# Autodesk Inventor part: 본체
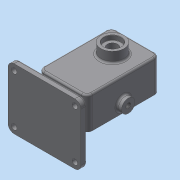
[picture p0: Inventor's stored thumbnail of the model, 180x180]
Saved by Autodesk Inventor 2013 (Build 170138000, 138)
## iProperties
Created: 2020-04
Part Number: 본체
Material: 일반
Document SubType Name: Modeling
Designer: dgall
Density: 1 g/cm^3
Author: dgall
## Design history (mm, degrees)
sketch "스케치1"
  geometry: L1 (-40, 60)-(40, 60); L2 (40, 60)-(40, -60); L3 (40, -60)-(-40, -60); L4 (-40, -60)-(-40, 60); 1 further point
  constraints: 8 end point, 2 parallel, 1 horizontal, 1 perpendicular
  dimensions: "d0" = 80 distance of L1.start L1.end; "d2" = 120 distance of L3.end L1.start; "d3" = 40 distance from line of L4 point (0, 0); "d4" = 60 distance from line of point (0, 0) L1
extrude "돌출1" new body sketch "스케치1" stored distance "d5" = 53; taper "d6" = 0 deg
fillet "모깎기1" dims "d7" = 9
node "작업 평면1"
sketch "스케치2"
  geometry: C1 r 19 at (0, 22); 1 further point
  constraints: 1 centre point, 1 vertical alignment
  dimensions: "d9" = 22 distance of point (0, 0) C1.centre; "d10" = 38 diameter of C1
extrude "돌출2" join sketch "스케치2" stored distance "d11" = 38 (= d10); taper "d12" = 0 deg
sketch "스케치3"
  geometry: L1 (-31, -60)-(31, -60) reference; L2 (-24, 22)-(-24, -22); L3 (24, 22)-(24, -22); A1 r 24 centre (0, 22) between (24, 22) and (-24, 22); A2 r 24 centre (0, -22) between (-24, -22) and (24, -22); 1 further point
  constraints: 4 end point, 4 point on circle, 2 centre point, 2 tangent, 2 vertical alignment, 1 parallel, 1 perpendicular
  dimensions: "d13" = 48 diameter of A1; "d16" = 48 diameter of A2; "d17" = 44 distance of A2.centre A1.centre; "d18" = 22 distance of point (0, 0) A1.centre
extrude "돌출3" cut sketch "스케치3" distance "d19" = 29; taper "d20" = 0 deg
sketch "스케치4"
  geometry: C1 r 12.5 at (0, 22); C2 r 12.5 at (0, -22); A1 r 24 centre (0, 22) between (24, 22) and (-24, 22) reference; A2 r 24 centre (0, -22) between (-24, -22) and (24, -22) reference; 1 further point
  constraints: 2 centre point, 2 coincident
  dimensions: "d21" = 25 diameter of C1; "d23" = 25 diameter of C2
extrude "돌출4" cut sketch "스케치4" distance "d24" = 15; taper "d25" = 0 deg
hole "구멍1" diameter "d28" = 17; stored, may be unused: countersink angle "d32" = 90 deg, drill point angle "d34" = 0 deg; dims "d26" = 10, "d27" = 10, "d29" = 6, "d30" = 28, "d31" = 7.3, "d33" = 8
sketch "스케치6"
  geometry: L1 (8, 43.5)-(36, 43.5) reference; L2 (36, 36.2)-(36, 43.5) reference; L3 (22, 42.8)-(36, 42.8); L4 (3, 43.5)-(41, 43.5) reference; L5 (36, 42.8)-(36.404, 43.5); L6 (22, 42.8)-(22, 43.5); 1 further point
  constraints: 6 end point, 2 point on line, 1 midpoint, 1 parallel
  dimensions: "d35" = 0.7 distance between parallel lines of L1 L3; "d36" = 30 deg angle of L2 L5; "d37" = 0.7 distance of L3.start L6.end
revolve "회전1" sketch "스케치6" stored, may be unused: angle "d38" = 90 deg
node "작업 평면2"
sketch "스케치11"
  geometry: L1 (51, -26.5)-(-51, -26.5) reference; C1 r 11 at (0, -12.5); 1 further point
  constraints: 1 centre point, 1 vertical alignment
  dimensions: "d59" = 22 diameter of C1; "d61" = 14 distance from line of C1.centre L1
extrude "돌출6" join sketch "스케치11" stored distance "d62" = 15; taper "d63" = 0 deg
hole "구멍3" diameter "d66" = 8.376; stored, may be unused: countersink angle "d70" = 90 deg, drill point angle "d72" = 0 deg; dims "d64" = 10, "d65" = 10, "d67" = 6, "d68" = 28, "d69" = 7.3, "d71" = 8
sketch "스케치12"
  geometry: L1 (-80, -56.5)-(-90, -56.5); L2 (-90, -56.5)-(-90, 43.5); L3 (-90, 43.5)-(-80, 43.5); L4 (-80, 43.5)-(-80, -56.5); L5 (3, 43.5)-(41, 43.5) reference; 1 further point
  constraints: 8 end point, 2 parallel, 1 horizontal, 1 horizontal alignment, 1 perpendicular
  dimensions: "d73" = 100 distance of L3.end L1.start; "d75" = 10 distance of L2.end L3.end; "d76" = 90 distance from line of L2 point (0, 0)
extrude "돌출7" join sketch "스케치12" stored distance "d77" = 120; taper "d78" = 0 deg
sketch "스케치13"
  geometry: L1 (24, -54.052)-(24, -86.78); L2 (-24, -54.052)-(-24, -86.78); L3 (24, -54.052)-(-24.009, -54.052); L4 (24, -86.78)-(-24, -86.78); 1 further point
  constraints: 8 end point, 2 parallel, 1 horizontal, 1 point on line, 1 vertical
  dimensions: "d79" = 48 distance between parallel lines of L2 L1; "d81" = 24 distance from line of L1 point (0, 0)
extrude "돌출8" join sketch "스케치13" stored distance "d82" = 53; taper "d83" = 0 deg
sketch "스케치14"
  geometry: L1 (-80, -56.5)-(-80, 43.5) reference; L2 (-60, -26.5)-(-80, -26.5) reference; L3 (-80, 26.5)-(-60, 26.5) reference; L4 (-60, 26.5)-(-60, -26.5) reference; L5 (-80, -26.5)-(-60, -14.953); L6 (-60, -14.953)-(-60, -26.5); L7 (-80, -26.5)-(-60, -26.5); 1 further point
  constraints: 6 end point, 2 collinear, 1 point on line
  dimensions: "d84" = 60 deg angle of L1 L5
extrude "돌출9" cut sketch "스케치14" stored distance "d85" = 53; taper "d86" = 0 deg
fillet "모깎기2" dims "d87" = 3
fillet "모깎기3" dims "d88" = 3
fillet "모깎기4" dims "d89" = 10
sketch "스케치17"
  geometry: C1 r 4.5 at (100, 90); A1 r 10 centre (100, 90) between (110, 90) and (100, 100) reference; 1 further point
  constraints: 1 centre point, 1 coincident
  dimensions: "d90" = 9 diameter of C1
extrude "돌출10" cut sketch "스케치17" distance "d92" = 53; taper "d93" = 0 deg
sketch "스케치18"
  geometry: C1 r 4.5 at (100, 10); A1 r 10 centre (100, 10) between (100, 0) and (110, 10) reference; 1 further point
  constraints: 1 centre point, 1 coincident
  dimensions: "d94" = 9 diameter of C1
extrude "돌출11" cut sketch "스케치18" distance "d96" = 53; taper "d97" = 0 deg
fillet "모깎기5" dims "d98" = 3
fillet "모깎기6" dims "d99" = 3
fillet "모깎기7" dims "d100" = 3
chamfer "모따기1" distance "d103" = 1; stored, may be unused: second distance "d104" = 2, angle "d105" = 45 deg
fillet "모깎기10" dims "d106" = 3
sketch "스케치20"
  geometry: A1 r 9 centre (-31, 51) between (-31, 60) and (-40, 51) reference; 2 further points
  constraints: 1 coincident
hole "구멍4" sketch "스케치20" at (-31, 51) diameter "d107" = 4.134; stored, may be unused: countersink angle "d111" = 90 deg, drill point angle "d113" = 118 deg; dims "d108" = 10, "d109" = 28, "d110" = 7.3, "d112" = 12
sketch "스케치21"
  geometry: L1 (110, -87)-(110, -7) reference; L2 (100, 3)-(0, 3) reference; 2 further points
  constraints: 1 other
  dimensions: "d123" = 60 distance from line of L1 point (50, -7); "d124" = 10 distance from line of L2 point (50, -7)
feature "엠보싱1" sketch "스케치21" dims "d125" = 0.5, "d126" = 0
fillet "모깎기11" dims "d127" = 0.5
node "솔리드1"
mirror "대칭2"
mirror "대칭3"
mirror "대칭4"
mirror "대칭5"
pattern_linear "직사각형 패턴1" dims "d116" = 62
pattern_linear "직사각형 패턴2" dims "d119" = 29
pattern_linear "직사각형 패턴3" dims "d122" = 73
other parameters: "d8" = 43.5, "d39" = -48
